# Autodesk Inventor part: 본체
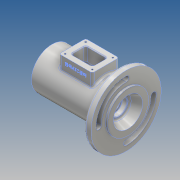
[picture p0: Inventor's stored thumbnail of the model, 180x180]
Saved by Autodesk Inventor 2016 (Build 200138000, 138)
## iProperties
Created: 2017-05
Part Number: 본체
Material: 알루미늄 6061
Document SubType Name: Modeling
Designer: Administrator
Density: 2.7 g/cm^3
Appearance: 알루미늄 - 평지
Mass: 677.219 g
Surface Area: 615.711 cm^2
Volume: 250.822 cm^3
Author: Administrator
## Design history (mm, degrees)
sketch "스케치2"
  geometry: L1 (-56, 0)-(59, 0); L2 (-56, 0)-(-56, 31); L3 (-56, 31)-(46, 31); L4 (46, 31)-(46, 53); L5 (46, 53)-(56, 53); L6 (56, 53)-(56, 31); L7 (56, 31)-(59, 31); L8 (59, 31)-(59, 0); 1 further point
  constraints: 16 end point, 5 perpendicular, 3 point on line, 1 horizontal, 1 vertical
  dimensions: "d1" = 115 distance of L1.start L1.end; "d2" = 3 distance between parallel lines of L6 L8; "d3" = 13 distance between parallel lines of L4 L8; "d4" = 106 diameter of L5 L1; "d5" = 62 diameter of L3 L1; "d6" = 56 distance from line of point (0, 0) L2
revolve "회전1" sketch "스케치2" stored, may be unused: angle "d7" = 90 deg
sketch "스케치3"
  geometry: L1 (-25, 20)-(25, 20); L2 (25, 20)-(25, -20); L3 (25, -20)-(-25, -20); L4 (-25, -20)-(-25, 20); L5 (-25, 20)-(25, -20); L6 (25, 20)-(-25, -20); 1 further point
  constraints: 12 end point, 2 midpoint, 2 parallel, 1 horizontal, 1 perpendicular
  dimensions: "d8" = 50 distance between parallel lines of L2 L4; "d9" = 40 distance between parallel lines of L3 L1
extrude "돌출1" join sketch "스케치3" distance "d10" = 44; taper "d11" = 0 deg
sketch "스케치5"
  geometry: L1 (-56, -31)-(-56, 31) reference; L2 (-56, 0)-(59, 0); L3 (59, -31)-(59, 31) reference; L4 (-56, 0)-(-56, 21); L5 (-56, 21)-(-47, 21); L6 (-47, 21)-(-47, 24); L7 (-47, 24)-(-44, 24); L8 (-44, 24)-(-44, 20); L9 (-44, 20)-(-35, 20); L10 (-35, 20)-(-35, 17.5); L11 (-35, 17.5)-(-31.75, 17.5); L12 (-31.75, 17.5)-(-31.75, 18.5); L13 (-31.75, 18.5)-(-30, 18.5); L14 (-30, 18.5)-(-30, 17.5); L15 (-30, 17.5)-(-19, 17.5); L16 (-19, 17.5)-(-19, 26); L17 (-19, 26)-(19, 26); L18 (19, 26)-(19, 17.5); L19 (19, 17.5)-(30, 17.5); L20 (30, 17.5)-(30, 16.5); L21 (30, 16.5)-(35, 16.5); L22 (35, 16.5)-(35, 10); L23 (35, 10)-(37.7, 10); L24 (37.7, 10)-(37.7, 12.5); L25 (37.7, 12.5)-(44.3, 12.5); L26 (46, -53)-(46, 53) reference; L27 (44.3, 12.5)-(45, 12.904); L28 (45, 12.904)-(45, 16); L29 (45, 16)-(59, 22); L30 (59, 22)-(59, 0); 2 further points
  constraints: 54 end point, 17 perpendicular, 4 point on line, 3 midpoint, 2 collinear, 2 vertical, 1 horizontal, 1 parallel, 1 vertical alignment
  dimensions: "d14" = 42 diameter of L5 L2; "d15" = 48 diameter of L7 L2; "d16" = 40 diameter of L9 L2; "d17" = 35 diameter of L11 L2; "d18" = 3 distance between parallel lines of L8 L6; "d19" = 12 distance between parallel lines of L8 L1; "d20" = 21 distance between parallel lines of L10 L1; "d21" = 37 diameter of L13 L2; "d22" = 1.75 distance from line of L14 L12.end; "d23" = 26 distance between parallel lines of L14 L4; "d24" = 11 distance between parallel lines of L16 L14; "d25" = 11 distance from line of L19.end L18; "d26" = 52 diameter of L17 L2; "d29" = 5 distance between parallel lines of L22 L20; "d31" = 2.7 distance between parallel lines of L24 L22; "d33" = 0.7 horizontal distance of L25.end L27.end; "d34" = 30 deg angle of L25 L27; "d35" = 14 distance from line of L29.end L28; "d36" = 44 diameter of L29.end L2; "d37" = 25 diameter of L25 L2; "d38" = 20 diameter of L23 L2; "d39" = 33 diameter of L21 L2; "d40" = 32 diameter of L28.end L2
revolve "회전2" sketch "스케치5" stored, may be unused: angle "d41" = 90 deg
sketch "스케치6"
  geometry: L1 (-16, 11)-(16, 11); L2 (16, 11)-(16, -11); L3 (16, -11)-(-16, -11); L4 (-16, -11)-(-16, 11); L5 (-16, 11)-(16, -11); L6 (16, 11)-(-16, -11); 1 further point
  constraints: 12 end point, 2 midpoint, 2 parallel, 1 horizontal, 1 perpendicular
  dimensions: "d42" = 32 distance of L2.end L3.end; "d43" = 22 distance of L1.end L2.end
extrude "돌출2" cut sketch "스케치6" stored distance "d44" = 44; taper "d45" = 0 deg; dims "d8" = 50, "d9" = 40
sketch "스케치7"
  geometry: L1 (25, 20)-(-25, 20) reference; L2 (-25, 20)-(-25, -20) reference; L3 (-25, -20)-(25, -20) reference; L4 (25, -20)-(25, 20) reference; L5 (0, 20)-(0, -20); L6 (-25, 0)-(25, 0); 5 further points
  constraints: 4 end point, 4 midpoint, 2 horizontal alignment, 2 symmetric about line, 2 vertical alignment
  dimensions: "d46" = 31 distance of point (-20.5, -15.5) point (-20.5, 15.5); "d47" = 41 distance of point (20.5, 15.5) point (-20.5, 15.5)
hole "구멍1" sketch "스케치7" at (-20.5, 15.5), (-20.5, -15.5), (20.5, -15.5), (20.5, 15.5) diameter "d48" = 2.459; stored, may be unused: countersink angle "d52" = 90 deg, drill point angle "d54" = 118 deg; dims "d49" = 6, "d50" = 4, "d51" = 2, "d53" = 8
sketch "스케치8"
  geometry: L1 (0, -45.5)-(0, 45.5); L2 (-45.5, 0.144)-(45.5, 0.144); C1 r 31 at (0, 0) reference; A1 r 4 centre (0, -41.5) between (0, -45.5) and (0, -37.5); A2 r 4 centre (-41.5, 0.144) between (-37.5, 0.134) and (-45.5, 0.144); A3 r 4 centre (0, 41.5) between (0, 45.5) and (0, 37.5); A4 r 4 centre (41.5, 0.144) between (37.5, 0.131) and (45.5, 0.144); A5 r 37.5 centre (0, 0) between (-37.5, 0.134) and (0, -37.5); A6 r 37.5 centre (0, 0) between (37.5, 0.131) and (0, 37.5); A7 r 45.5 centre (0, 0) between (-45.5, 0.144) and (0, -45.5); A8 r 45.5 centre (0, 0) between (45.5, 0.144) and (0, 45.5)
  constraints: 17 point on circle, 8 centre point, 4 end point, 4 point on line, 3 equal radius, 2 coincident, 1 horizontal
  dimensions: "d57" = 37.5 radius of A6; "d58" = 37.5 radius of A5; "d59" = 45.5 radius of A7; "d60" = 45.5 radius of A8; "d61" = 4 radius of A3
extrude "돌출3" cut sketch "스케치8" stored distance "d62" = 44; taper "d63" = 0 deg
chamfer "모따기1" distance "d64" = 1; stored, may be unused: second distance "d65" = 2, angle "d66" = 45 deg
fillet "모깎기1" dims "d67" = 3
fillet "모깎기2" dims "d68" = 0.3
sketch "스케치9"
  geometry: L1 (0, 20.315)-(50, 20.315) reference; L2 (-31, -54.685)-(-31, 7.315) reference; 2 further points
  constraints: 1 other
  dimensions: "d69" = 8 distance from line of point (25, 12.315) L1; "d70" = 56 distance from line of point (25, 12.315) L2
feature "엠보싱1" sketch "스케치9" dims "d1" = 115, "d2" = 3, "d3" = 13, "d4" = 106, "d5" = 62, "d6" = 56, "d71" = 0.5, "d72" = 0
fillet "모깎기3" dims "d73" = 3
fillet "모깎기4" dims "d74" = 3
chamfer "모따기2" distance "d75" = 1; stored, may be unused: second distance "d76" = 2, angle "d77" = 45 deg
feature "스레드1" dims "d78" = 10, "d79" = 0
chamfer "모따기3" distance "d80" = 1; stored, may be unused: second distance "d81" = 2, angle "d82" = 45 deg
node "솔리드1"
other parameters: "d55" = 91, "d56" = 75
